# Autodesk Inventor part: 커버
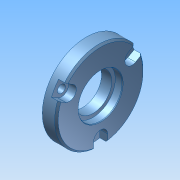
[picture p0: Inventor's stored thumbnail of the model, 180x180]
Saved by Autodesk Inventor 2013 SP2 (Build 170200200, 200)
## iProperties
Created: 2025-10
Part Number: 커버
Material: Generic
Document SubType Name: Modeling
Designer: a
Density: 1 g/cm^3
Author: a
변환 표준: STEP AP214IS
전처리기: Build: 200, Release: 2013 SP2 Update 6 - Date: Thu 07/17/2014
전송 단위: 밀리미터
불확실성: 0.01
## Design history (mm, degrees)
node "커버1"
node "솔리드1"
node "기준1"
